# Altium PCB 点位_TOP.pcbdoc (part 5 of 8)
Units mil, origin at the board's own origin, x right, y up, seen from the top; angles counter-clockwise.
Board outline 5129 x 4161 mil, 8 copper layers (Top Layer, GND1, 内层2, VCC, 内层4, Inner5, GND2, Bottom Layer); 288 components, 452 nets, 2040 pads, 1119 vias.
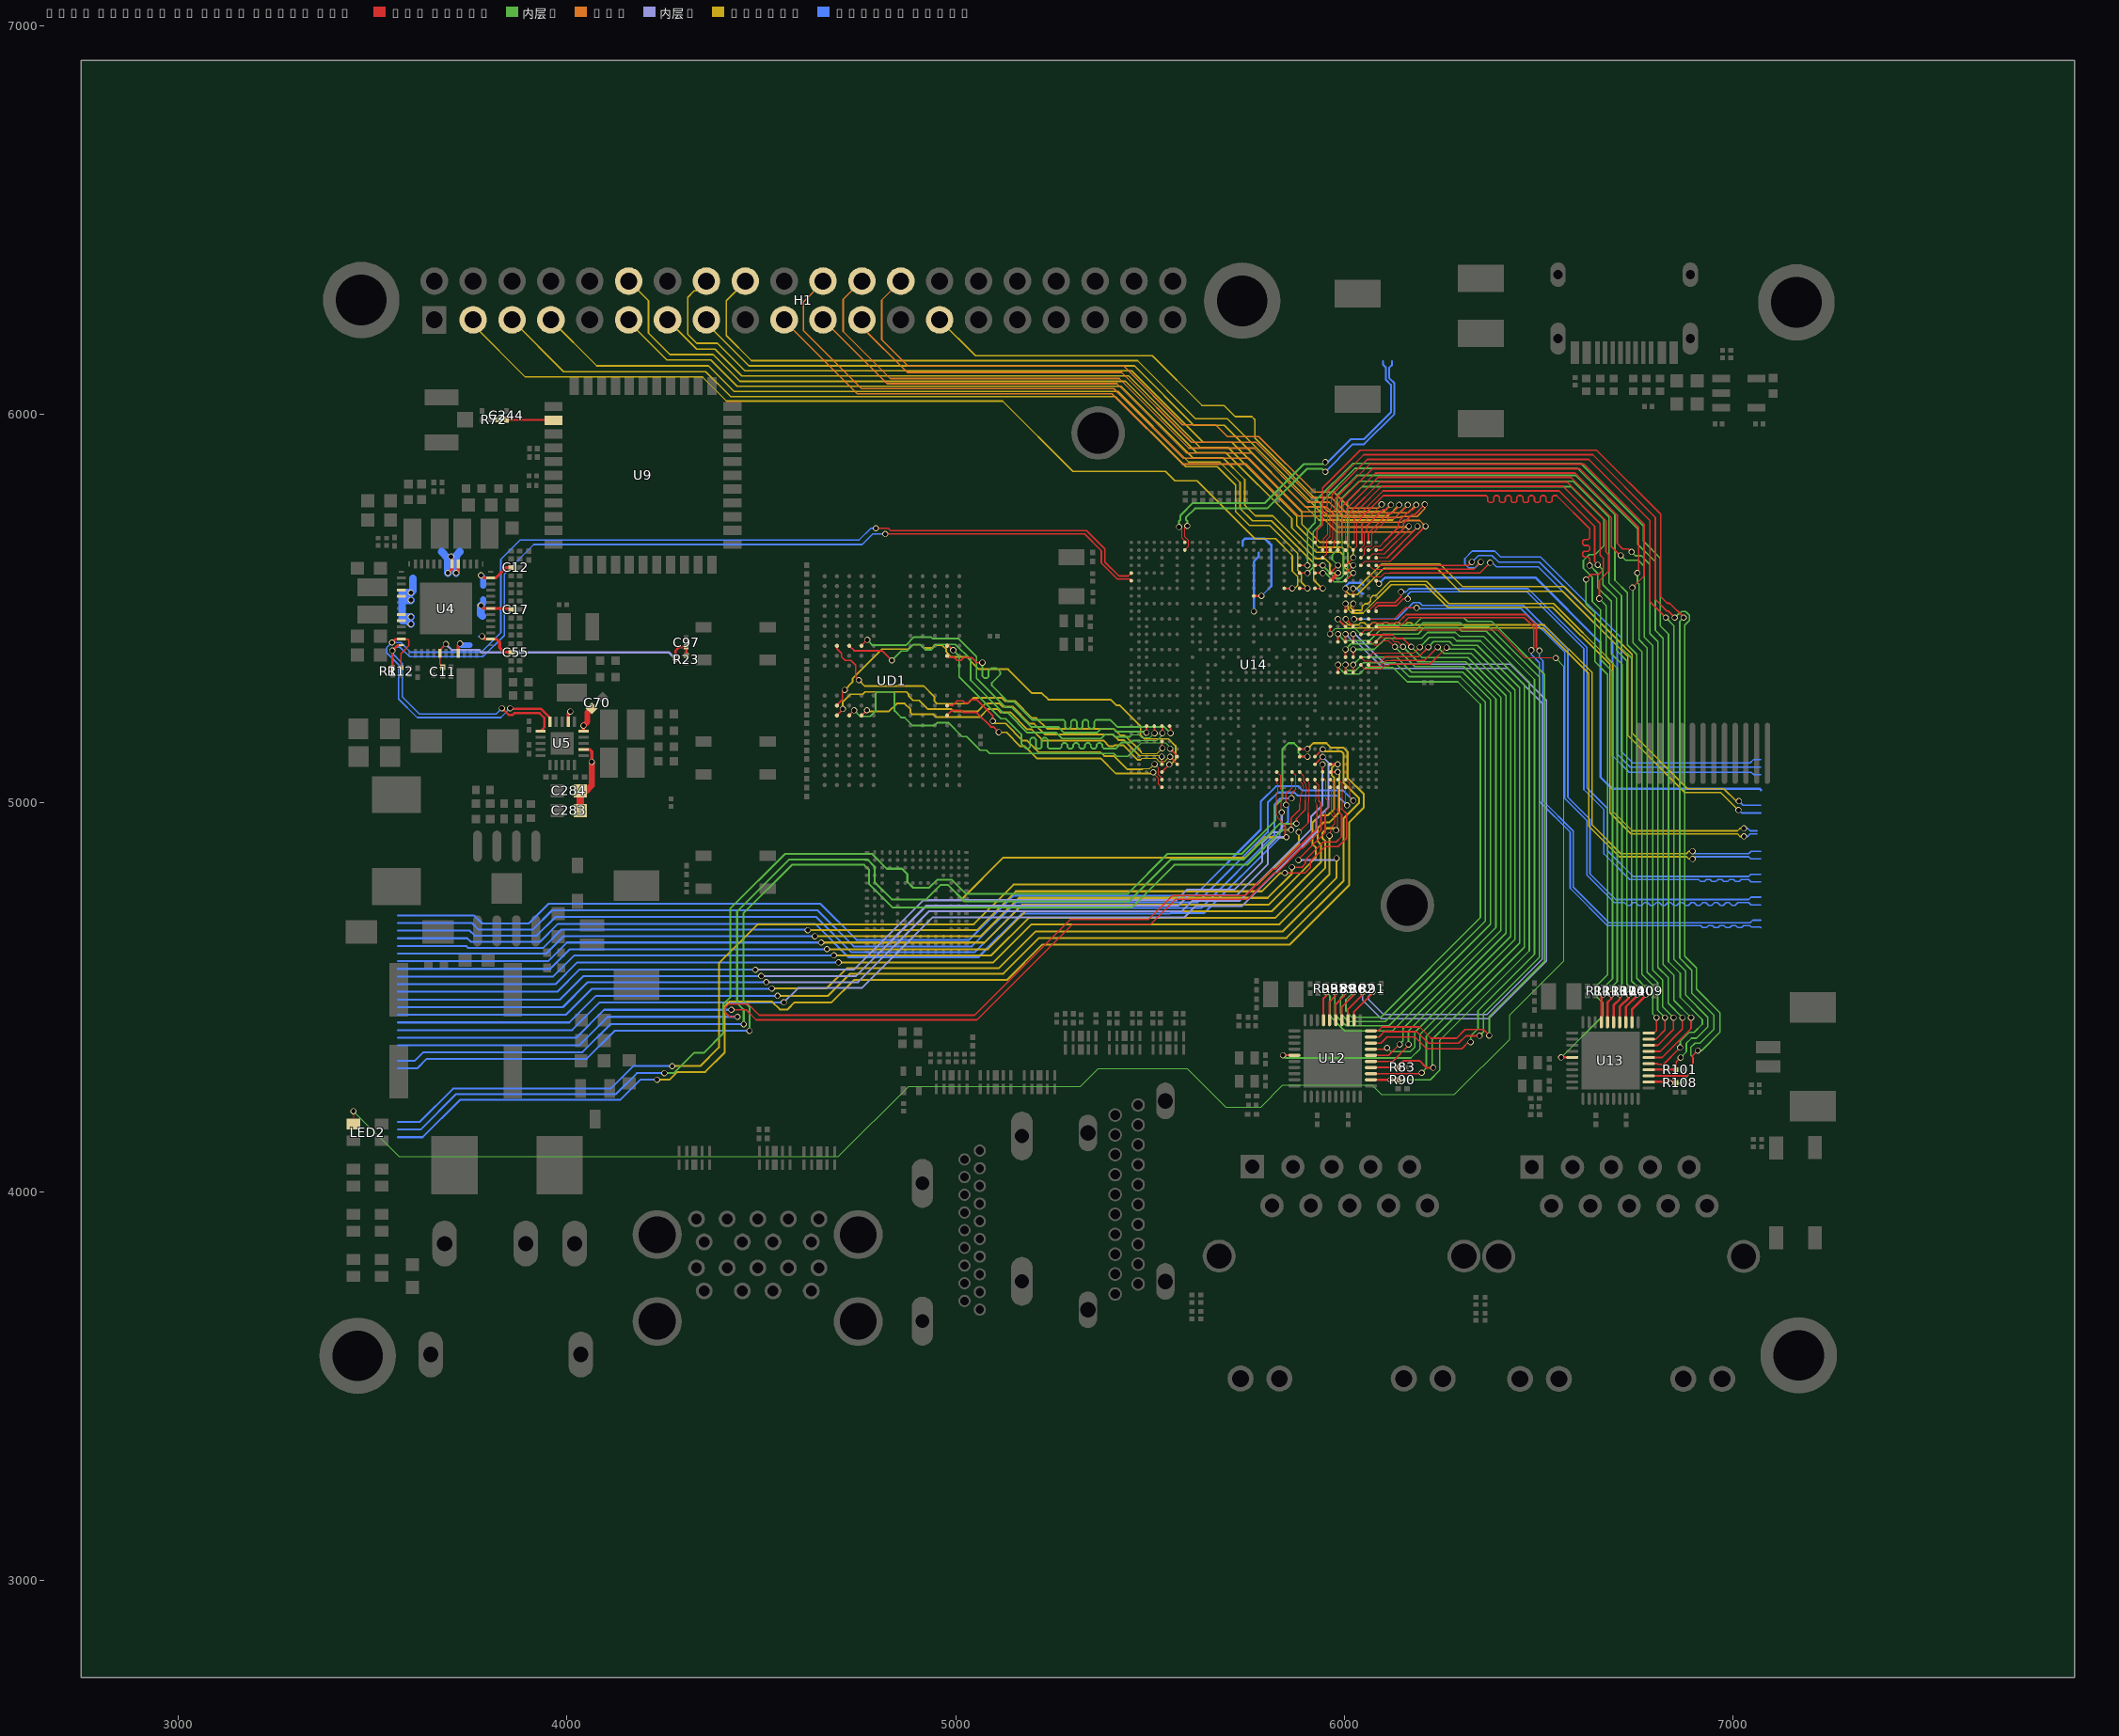
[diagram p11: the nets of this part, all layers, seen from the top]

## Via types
v1: diameter 15.75, hole 11.8, Top Layer to Bottom Layer, 496 vias
v2: diameter 15.7, hole 11.8, Top Layer to Bottom Layer, 335 vias
v3: diameter 15.75, hole 11.81, Top Layer to Bottom Layer, 279 vias
v4: diameter 24, hole 12, Top Layer to Bottom Layer, 9 vias

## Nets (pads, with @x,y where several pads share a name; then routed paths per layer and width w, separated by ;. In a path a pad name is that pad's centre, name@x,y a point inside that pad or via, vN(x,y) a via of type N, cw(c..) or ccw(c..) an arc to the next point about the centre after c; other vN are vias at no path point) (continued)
LCD0-D6: U14.E32 | length 2810.2
  Top Layer w3: U14.E32@6003.23,5060.51 6012.98,5050.75 6012.98,5016.02 v1(6023,5006)
  Bottom Layer w5: 3564.97,4711.06 3760.93,4711.06 3782,4690 3902,4690 3953,4741 4652,4741 4745,4648 5035,4648 5148,4761 5614,4761 5785,4932 5785,5004 5824,5043 5881,5043 5892,5032 5997,5032 v1(6023,5006)
LCD0-D7: U14.E33 | length 2779.1
  Top Layer w3: U14.E33@6003.18,5040.81 6003.18,4997.82 v1(6007,4994)
  Bottom Layer w5: 3564.97,4691.38 3755.62,4691.38 3773,4674 3912,4674 3962,4724 4645,4724 4738,4631 5042,4631 5156,4745 5623,4745 5803,4925 5803,5001 5829,5027 5872,5027 5880,5019 5982,5019 v1(6007,4994)
LCD0-D8: U14.M31 | length 2648.4
  Top Layer w3: U14.M31@5865.45,5080.07 5875.25,5070.27 5875.25,5035.39 5870.86,5031
  Top Layer w4: v1(5864,5012) 5864,5024.14 5870.86,5031
  Bottom Layer w5: 3564.97,4671.69 3750.3,4671.69 3763,4659 3923,4659 3971,4707 4641,4707 4732,4616 5049,4616 5163,4730 5632,4730 5820,4918 5820,4996 5836,5012 v1(5864,5012)
LCD0-D9: U14.M32 | length 2621.5
  Top Layer w3: 5856,5030 5865.45,5039.45 U14.M32@5865.45,5060.37
  Top Layer w4: v1(5850,4995) 5850,5024 5856,5030
  Bottom Layer w5: 3564.97,4652.01 3743.99,4652.01 3753,4643 3931,4643 3977,4689 4639,4689 4725,4603 5058,4603 5170,4715 5551,4715 5553,4717 5640,4717 5834,4911 5834,4931 5855,4952 5855,4990 v1(5850,4995)
LCD0-D10: U14.F32 | length 2730.5
  Top Layer w3: U14.F32@5983.53,5060.51 5993.34,5050.71 5993.34,4985.27
  Top Layer w4: v1(5847,4820) 5899,4820 5913,4834 5913,4850 5951,4888 5984,4888 6006,4910 6006,4972.6 5993.34,4985.27
  Inner5 w5: v1(4620,4673) 5055,4673 5155,4773 5788,4773 5835,4820 v1(5847,4820)
  Bottom Layer w5: 3564.97,4632.32 3740.68,4632.32 3746,4627 3938,4627 3985,4674 4619,4674 v1(4620,4673)
LCD0-D11: U14.F33 | length 2699.4
  Top Layer w3: 5983.48,4985.23 U14.F33@5983.48,5040.81
  Top Layer w4: v1(5865,4835) 5891,4835 5900,4844 5900,4854 5946,4900 5979,4900 5993,4914 5993,4970.05 5983.48,4979.57 5983.48,4985.23
  Inner5 w5: v1(4638,4657) 5064,4657 5163,4756 5803,4756 5865,4818 v1(5865,4835)
  Bottom Layer w5: 3564.97,4612.64 3946.64,4612.64 3991,4657 v1(4638,4657)
LCD0-D12: U14.G30 | length 2782.1
  Top Layer w5: U14.G30@5963.83,5099.56 v1(5982.83,5099.56)
  Inner5 w5: v1(4654,4641) 5074,4641 5171,4738 5805,4738 5927,4860 5927,4885 5918,4894 5918,4949 5937,4968 5957,4968 5974,4985 5974,5065 5968,5071 5968,5091 5976.56,5099.56 v1(5982.83,5099.56)
  Bottom Layer w5: 3564.97,4592.95 3951.95,4592.95 4000,4641 v1(4654,4641)
LCD0-D13: U14.G31 | length 2777.1
  Top Layer w5: U14.G31@5963.83,5079.87 v1(5982.83,5079.87)
  Inner5 w5: v1(4669,4624) 5083,4624 5181,4722 5814,4722 5940,4848 5940,4893 5931,4902 5931,4935 5946,4950 5961,4950 5987,4976 5987,5075.71 v1(5982.83,5079.87)
  Bottom Layer w5: 3564.97,4573.27 3957.26,4573.27 4008,4624 v1(4669,4624)
LCD0-D14: U14.G32 | length 2777.4
  Top Layer w3: U14.G32@5963.88,5060.51 5973.7,5050.69 5973.7,4973.3 5983,4964 5983,4934 v1(5979,4930)
  Inner5 w5: v1(4687,4608) 5092,4608 5189,4705 5823,4705 5951,4833 5951,4902 5944,4909 5944,4924 5955,4935 5974,4935 v1(5979,4930)
  Bottom Layer w5: 3564.97,4553.59 3964.59,4553.59 4019,4608 v1(4687,4608)
LCD0-D15: U14.G33 | length 2745.5
  Top Layer w3: U14.G33@5963.82,5040.51 5966,5038.33 5966,4971 5975,4962 5975,4946 5965,4936 5965,4926 5962,4923 5962,4921 v1@5963.88,4922.88
  Inner5 w5: v1(4699,4590) 5097,4590 5195,4688 5833,4688 5962,4817 v1(5962,4916)
  Bottom Layer w5: 3564.97,4533.9 3970.89,4533.9 4027,4590 v1(4699,4590)
LCD0-D16: U14.P31 | length 2635
  Top Layer w3: U14.P31@5826.15,5080.07 5835.95,5070.27 5835.95,5036.61 5836.36,5036.2 5839.08,5025.26 5839.15,5007.57 5836.45,4999.92 5836.99,4988.57 v1(5839,4976)
  Top Layer w4: v1@5836,4979 v1(5839,4976)
  内层4 w5: v1(4485,4571) 4738,4571 4917,4750 5568,4750 5595,4777 5717,4777 5789,4849 5789,4898 5816,4925 5835,4925 5839,4929 v1(5839,4976)
  Bottom Layer w5: 3564.97,4514.22 3975.22,4514.22 4032,4571 v1(4485,4571)
LCD0-D17: U14.P32 | length 3543
  Top Layer w3: U14.P32@5826.14,5058.6 5828.27,5050.09 5829.02,5046.25 5829.37,5036.98 5829.13,5028.15 5829.13,5028.04 5826,5024.91 5826,4969.64 5828.24,4963.11 5833.8,4956.24 ; 5833.78,4956.22 5846,4944
  Top Layer w4: 5846,4944 5848,4942 5848,4915 v1(5851,4912)
  内层4 w5: v1(4500,4555) 4744,4555 4925,4736 5573,4736 5600,4763 5724,4763 5803,4842 5803,4888 5827,4912 v1(5851,4912)
  Inner5 w5: 5017,4754 5122,4859 5743,4859 5796,4912 v1(5851,4912)
  Bottom Layer w5: 3564.97,4494.52 3982.53,4494.52 4043,4555 v1(4500,4555)
LCD0-D18: U14.H31 | length 2737
  Top Layer w4: v1(5944,5099) 5944.15,5098.85 U14.H31@5944.15,5079.88
  内层4 w5: v1(4513,4539) 4749,4539 4931,4721 5581,4721 5608,4748 5730,4748 5915,4933 5915,4966 5944,4995 v1(5944,5099)
  Bottom Layer w5: 3564.97,4474.85 3989.84,4474.85 4054,4539 v1(4513,4539)
LCD0-D19: U14.H32 | length 2961.3
  Top Layer w3: U14.H32@5944.18,5060.51 5945.1,5061.43 5950,5061.43 5953,5058.43 5953,5010.7 5958.74,5004.96 5958.74,4985.74 5951,4978 5951,4971
  Top Layer w4: v1(5882,4853) 5882,4855 5951,4924 5951,4971
  内层4 w5: v1(5882,4853) 5975,4853 v1(5980,4858)
  Inner5 w5: v1(4527,4523) 4668,4523 4720,4575 5111,4575 5206,4670 5842,4670 5980,4808 v1(5980,4858)
  Bottom Layer w5: 3564.97,4455.15 3997.16,4455.15 4064,4522 4526,4522 v1(4527,4523)
LCD0-D20: U14.J29 | length 3030.2
  Top Layer w4: U14.J29@5924.46,5119.25 5943.46,5138.25 v1(5944.46,5138.25)
  Inner5 w5: v1(4542,4504) 4672,4504 4729,4561 5123,4561 5215,4653 5851,4653 5998,4800 5998,4960 6038,5000 6038,5012 5998,5052 5998,5127 5992,5133 5949.71,5133 v1(5944.46,5138.25)
  Bottom Layer w5: 3564.97,4435.48 4006.47,4435.48 4075,4504 v1(4542,4504)
LCD0-D21: U14.J30 | length 2813.7
  Top Layer w4: U14.J30@5924.46,5099.56 5943.46,5118.56 v1(5944.46,5118.56)
  内层4 w5: v1(4558,4487) 4595,4524 4759,4524 4941,4706 5589,4706 5618,4735 5737,4735 5928,4926 5928,4958 5959,4989 5959,5104.02 v1(5944.46,5118.56)
  Bottom Layer w5: 3564.97,4415.78 4013.78,4415.78 4085,4487 v1(4558,4487)
LCD0-D22: U14.J32 | length 2754.7
  Top Layer w3: U14.J32@5924.48,5060.51 5924.48,5054.71 5934.27,5044.91 5934.27,5005.56
  Top Layer w4: v1(4423,4468) 4461,4468 4487,4442 5055,4442 5301,4688 5502,4688 5566,4752 5751,4752 5819,4820 5826,4820 5890,4884 5894,4884 5940.04,4930.04 5940.04,4999.8 5934.27,5005.56
  Bottom Layer w5: 3564.97,4396.1 4024.11,4396.1 4096,4468 v1(4423,4468)
LCD0-D23: U14.J33 | length 2797.3
  Top Layer w3: U14.J33@5924.31,5040.15 5926.01,5034.28 5926.16,5014.28 5925.23,5003.47 5929.75,4994.05
  Top Layer w4: v1(4439,4450) 4419,4450 4408,4461 4408,4474 4417,4483 4466,4483 4495,4454 5049,4454 5295,4700 5496,4700 5558,4762 5746,4762 5814,4830 5823,4830 5887,4894 5890,4894 5929.75,4933.75 5929.75,4994.05 5929.75,4994.35
  Bottom Layer w5: 3564.97,4376.41 4031.41,4376.41 4105,4450 v1(4439,4450)
LCD0-DE: U14.K32 | length 2919.7
  Top Layer w3: 5906.88,4974.2 5906.88,4997.45 5908.54,5020.82 5908.56,5021.22 5907.94,5033.02 5908.5,5041.47 5908.53,5048.86 5904.77,5060.51 U14.K32@5907.18,5058.11
  Top Layer w4: v1(5883,4925) 5907.18,4949.18 5907.18,4974
  Inner5 w5: v1(4271,4323) 4343,4323 4391,4371 4391,4588 4491,4688 5047,4688 5149,4790 5776,4790 5883,4897 v1(5883,4925)
  Bottom Layer w5: 3564.97,4179.56 3621.57,4179.56 3707,4265 4113,4265 4171,4323 v1(4271,4323)
LCD0-HSYNC: U14.L28 | length 3317
  Top Layer w5: U14.L28@5885.09,5138.93 v1(5905.09,5138.93)
  Inner5 w5: v1(4232,4288) 4264,4288 4284,4308 4356,4308 4406,4358 4406,4477 4418,4489 4528,4489 4548,4469 4568,4469 4586,4487 4681,4487 4739,4545 5132,4545 5223,4636 5860,4636 6012,4788 6012,4950 6050,4988 6050,5023 6008.32,5064.68 6008.32,5131.68 5997,5143 5965,5143 5954,5154 5920.16,5154 v1(5905.09,5138.93)
  Bottom Layer w5: 3564.97,4140.19 3629.2,4140.19 3725,4236 4137,4236 4189,4288 v1(4232,4288)
LCD0-PWM: U14.L31 | length 3050.8
  Top Layer w3: U14.L31@5885.15,5080.07 5894.98,5070.24 5895.03,5059.01 5896.04,5055.11 5898.18,5052.43 5901.72,5040.93 5898.86,5017.8 5899,5005.68 5899.01,5005.17
  Top Layer w4: v1(5877,4947) 5877,4960 5899,4982 5899,5005.68 5899,5006
  内层2 w5: v1(4455,4431) 4455,4468 4438,4485 4438,4721 4572,4855 4773,4855 4792,4836 4792,4796 4836,4752 4924,4752 4961,4789 4981,4789 5023,4747 5446,4747 5554,4855 5742,4855 5834,4947 v1(5877,4947)
  Bottom Layer w5: 3564.97,4337.05 3609.05,4337.05 3631,4359 4040,4359 4112,4431 v1(4455,4431)
LCD0-RST: U14.L32 | length 3006.3
  Top Layer w3: U14.L32@5884.76,5058.85 5892.33,5049.35 5894.8,5041.31 5893.95,5034.44 5891.48,5029.57 5887.54,5020.69 5884.84,4996.2
  Top Layer w4: v1(5863,4931) 5863,4961 5884.8,4982.8 5884.8,4996.42
  内层2 w5: v1(4470,4414) 4470,4476 4454,4492 4454,4716 4579,4841 4765,4841 4777,4829 4777,4792 4838,4731 5453,4731 5563,4841 5750,4841 5840,4931 v1(5863,4931)
  Bottom Layer w5: 3564.97,4317.36 3615.36,4317.36 3640,4342 4051,4342 4123,4414 v1(4470,4414)
LCD0-VSYNC: U14.L29 | length 3182.7
  Top Layer w5: U14.L29@5885.09,5119.25 v1(5905.09,5119.25)
  内层2 w5: v1(4251,4305) 4275,4305 4327,4357 4352,4357 4402,4407 4402,4482 4420,4500 4420,4728 4561,4869 4785,4869 4823,4831 4862,4831 4876,4817 4876,4797 4891,4782 4932,4782 4953,4803 4990,4803 5027,4766 5442,4766 5545,4869 5736,4869 5823,4956 5823,4993 5841,5011 5841,5139 5856,5154 5870.33,5154 5882,5142.33 5882,5129 5891.75,5119.25 v1(5905.09,5119.25)
  Bottom Layer w5: 3564.97,4159.89 3623.89,4159.89 3715,4251 4126,4251 4180,4305 v1(4251,4305)
LEDC: LED2.3 U14.C13 | length 4864.7
  Top Layer w3: v2(3451,4207) 3451.16,4206.84 LED2.3@3451.16,4174.43 ; U14.C13@6042.57,5434.21 6052.36,5444 6395,5444 6466,5373 v2(6544,5373)
  内层2 w3: v2(3451,4207) 3569,4089 4697,4089 4878,4270 5320,4270 5366,4316 5597,4316 5696,4217 5784,4217 5840,4273 6072,4273 6096,4249 6282,4249 6424,4391 6424,4453 6564,4593 6564,5353 v2(6544,5373)
MCSI0-CKN: U14.A10 | length 1629.1
  Top Layer w4: U14.A10@6081.94,5493.27 6079.93,5495.28 6079.93,5500.93 6087,5508 6134.16,5508 6151.16,5525 v2(6163,5525)
  Bottom Layer w4: v2(6163,5525) 6163,5536 6170.34,5543.34 6469.66,5543.34 6616,5397 6616,5035 6668,4983 6668,4869 6734.06,4802.94 6911.21,4802.94 6916.21,4797.94 6926.21,4797.94 6931.21,4802.94 6941.21,4802.94 6946.21,4797.94 6956.21,4797.94 6961.21,4802.94 6971.21,4802.94 6976.21,4797.94 6986.21,4797.94 6991.21,4802.94 7001.21,4802.94 7006.21,4797.94 7016.21,4797.94 7021.21,4802.94 7040.56,4802.94 7046.4,4797.1 7072.02,4797.1
MCSI0-CKP: U14.B10 | length 1625.8
  Top Layer w4: U14.B10@6062.26,5493.26 6062.26,5494.33 6083.93,5516 6130.84,5516 6146,5531.16 v2(6146,5543)
  Bottom Layer w4: v2(6146,5543) 6158.69,5543 6167.03,5551.34 6472.66,5551.34 6624,5400 6624,5039 6677,4986 6677,4877 6743.06,4810.94 7040.56,4810.94 7046.4,4816.78 7072.02,4816.78
MCSI0-D0N: U14.A12 | length 1690.5
  Top Layer w3: U14.A12@6081.94,5453.9 6141.9,5453.9 6158,5470
  Top Layer w4: 6158,5470 6165,5477 6463,5477 6487,5453 6487,5399 v2(6481,5393)
  Bottom Layer w4: v2(6481,5393) 6481,5382 6502,5361 6502,5004 6581,4925 6581,4780.69 6676.69,4685 6916.73,4685 6921.73,4680 6931.73,4680 6936.73,4685 6946.73,4685 6951.73,4680 6961.73,4680 6966.73,4685 6976.73,4685 6981.73,4680 6991.73,4680 6996.73,4685 7006.73,4685 7011.73,4680 7021.73,4680 7026.73,4685 7043,4685 7047,4681 7070.02,4681 7072.02,4678.99
MCSI0-D0P: U14.B12 | length 1692.6
  Top Layer w3: U14.B12@6062.26,5453.91 6072.36,5464 6138,5464 6150,5476
  Top Layer w4: 6150,5476 6159,5485 6466.31,5485 6494,5457.31 6494,5400 v2(6502,5392)
  Bottom Layer w4: v2(6502,5392) 6502,5375 6511,5366 6511,5006 6589,4928 6589,4784 6681,4692 7044,4692 7050.68,4698.68 7072.02,4698.68
MCSI0-D1N: U14.B11 | length 1700.5
  Top Layer w3: U14.B11@6062.26,5473.58 6128.58,5473.58 6137,5482
  Top Layer w4: 6137,5482 6157,5502 v2(6186,5502)
  Bottom Layer w4: v2(6186,5502) 6187.68,5500.32 6454.68,5500.32 6567.05,5387.95 6567.05,5011.95 6624,4955 6624,4814.53 6694.64,4743.89 6720.08,4743.89 6727.33,4736.65 6735.08,4736.65 6742.33,4743.89 6750.08,4743.89 6757.33,4736.65 6765.08,4736.65 6772.33,4743.89 6780.08,4743.89 6787.33,4736.65 6795.08,4736.65 6802.33,4743.89 6810.08,4743.89 6817.33,4736.65 6825.08,4736.65 6832.33,4743.89 6840.08,4743.89 6847.33,4736.65 6855.08,4736.65 6862.33,4743.89 6870.08,4743.89 6877.33,4736.65 6885.08,4736.65 6892.33,4743.89 6900.08,4743.89 6907.33,4736.65 6915.08,4736.65 6922.33,4743.89 6930.08,4743.89 6937.33,4736.65 6945.08,4736.65 6952.33,4743.89 6960.08,4743.89 6967.33,4736.65 6975.08,4736.65 6982.33,4743.89 6990.08,4743.89 6997.33,4736.65 7005.08,4736.65 7012.33,4743.89 7040.56,4743.89 7046.4,4738.05 7072.02,4738.05
MCSI0-D1P: U14.C11 | length 1705.2
  Top Layer w5: v2(6025,5473) 6042,5473 U14.C11@6042.58,5473.58
  Bottom Layer w4: v2(6025,5473) 6135,5473 6177.35,5515.35 6193.65,5515.35 6200.68,5508.32 6460.68,5508.32 6575.05,5393.95 6575.05,5014.95 6632,4958 6632,4817.84 6697.95,4751.89 7040.56,4751.89 7046.4,4757.73 7072.02,4757.73
MCSI0-D2N: U14.E12 | length 1606.8
  Top Layer w4: v1(5983.2,5472.9) 5984.2,5472.9 U14.E12@6003.2,5453.9
  Inner5 w4: v1(5983.2,5472.9) 6005.75,5450.34 6511.34,5450.34 6629,5332.69 6629,4940.69 6707.69,4862 6880.15,4862 6886.15,4856 v2(6896,4856)
  Bottom Layer w4: v2(6896,4856) 6902,4862 7040.56,4862 7046.4,4856.15 7072.02,4856.15
MCSI0-D2P: U14.D12 | length 1607.1
  Top Layer w4: v1(6004,5473) 6022.9,5454.1 U14.D12@6022.9,5453.9
  Inner5 w4: v1(6004,5473) 6004,5465 6010.66,5458.34 6036.66,5458.34 6041.66,5463.34 6051.66,5463.34 6056.66,5458.34 6066.66,5458.34 6071.66,5463.34 6081.66,5463.34 6086.66,5458.34 6096.66,5458.34 6101.66,5463.34 6111.66,5463.34 6116.66,5458.34 6126.66,5458.34 6131.66,5463.34 6141.66,5463.34 6146.66,5458.34 6156.66,5458.34 6161.66,5463.34 6171.66,5463.34 6176.66,5458.34 6514.66,5458.34 6637,5336 6637,4944 6711,4870 6880.15,4870 6886.15,4876 v2(6896,4876)
  Bottom Layer w4: v2(6896,4876) 6902,4870 7040.56,4870 7046.4,4875.85 7072.02,4875.85
MCSI0-D3N: U14.E10 | length 1619.2
  Top Layer w4: v1(6003,5513) 6003,5493.47 U14.E10@6003.2,5493.27
  Inner5 w4: v1(6003,5513) 6010,5506 6010,5498.1 6019.44,5488.66 6047.66,5488.66 6121,5562 6208,5562 6266,5504 6536,5504 6683,5357 6683,4974.69 6737.38,4920.3 7011.55,4920.3 7017.86,4914 v2(7028,4914)
  Bottom Layer w4: v2(7028,4914) 7037.85,4914 7044.15,4920.3 7062.34,4920.3
MCSI0-D3P: U14.D10 | length 1616.6
  Top Layer w4: U14.D10@6022.9,5493.27 6022.9,5512.9 v1(6023,5513)
  Inner5 w4: v1(6023,5513) 6017,5507 6017,5501 6022.34,5495.66 6043.34,5495.66 6046.01,5498.33 6046.01,5506.01 6052.78,5512.78 6060.46,5512.78 6067.23,5519.54 6067.23,5527.23 6073.99,5533.99 6081.68,5533.99 6117.69,5570 6211.31,5570 6268.31,5513 6538.31,5513 6691,5360.31 6691,4978 6740.7,4928.3 7011.55,4928.3 7017.86,4934.61 v2(7027.71,4934.61)
  Bottom Layer w4: v2(7027.71,4934.61) 7037.85,4934.61 7044.15,4928.3 7062.34,4928.3
MCSI0-MCLK: U14.A6 | length 1429.7
  Top Layer w6: U14.A6@6081.94,5572.01 6081.94,5571.06 v2(6089,5564)
  Bottom Layer w6: v2(6089,5564) 6105,5580 6492,5580 6659,5413 6659,5067 6689.89,5036.11 7069.24,5036.11 7072.02,5033.32
MCSI0-PWDN: U14.B4 | length 1534
  Top Layer w3: U14.B4@6064.06,5610.26 6074.92,5601.77 6084.19,5601.46 6089.96,5601.82 6105.25,5601.87
  Top Layer w4: 6104.98,5602 6333,5602 v2(6351,5620)
  Bottom Layer w4: v2(6351,5620) 6336,5605 6320,5605 6310,5615 6310,5629 6329,5648 6387,5648 6402,5633 6505,5633 6713,5425 6713,5132 6742,5103 7044,5103 7053.06,5112.06 7072.02,5112.06
MCSI0-RSTN: U14.A4 | length 1398.5
  Top Layer w4: U14.A4@6081.94,5611.39 6319.39,5611.39 v2(6328,5620)
  Bottom Layer w4: v2(6328,5620) 6345,5637 6380,5637 6397,5620 6502,5620 6702,5420 6702,5126 6735.62,5092.38 7072.02,5092.38
MCSI0-SCK: U14.E8 | length 1561.8
  Top Layer w4: U14.E8@6003.2,5532.64 v1(6003.2,5551.64)
  Inner5 w4: v1(6003.2,5551.64) 6003.2,5545.8 6013,5536 6034,5536 6102,5604 6238,5604 6297,5545 6561,5545 6729,5377 6729,5174 6876,5027 6968,5027 7013,4982 v2(7014,4982)
  Bottom Layer w4: v2(7014,4982) 7021.73,4974.27 7072.02,4974.27
  Bottom Layer w6: v1(6003.2,5551.64) 6003.2,5557.2 6012,5566 6044.49,5566 6048.49,5562
MCSI0-SDA: U14.D8 | length 1501.4
  Top Layer w4: U14.D8@6022.89,5532.64 v1(6022.89,5551.64)
  Inner5 w4: v1(6022.89,5551.64) 6032.64,5551.64 6096,5615 6246,5615 6304,5557 6566,5557 6740,5383 6740,5180 6883,5037 6976,5037 7008,5005 v2(7015,5005)
  Bottom Layer w4: v2(7015,5005) 7026.05,4993.95 7072.02,4993.95
  Bottom Layer w6: v1(6022.89,5551.64) 6032.36,5551.64 6045,5539 6048.49,5539
MCSI0-USER: U14.B5 | length 1427.4
  Top Layer w3: U14.B5@6062.26,5591.69 6071.95,5582 6094,5582 6104,5592 6115.91,5592
  Top Layer w4: 6115.91,5592 6349,5592 v2(6375,5618)
  Bottom Layer w4: v2(6375,5618) 6381,5618 6391,5608 6499,5608 6690,5417 6690,5122 6733,5079 7047,5079 7053.31,5072.69 7072.02,5072.69
MICIN3N: U14.AF1 | length 869.5
  Top Layer w3: v1(5575,5710) 5576.32,5710 5582.69,5703.63 5582.69,5681.54 5589.69,5674.54 U14.AF1@5589.69,5670.41
  内层2 w5: v1(5575,5710) 5575,5725.71 5578.5,5729.21 5578.5,5740.01 5610.49,5772 5796,5772 5896,5872 5946,5872 v2(5951,5877)
  Bottom Layer w5: v2(5951,5877) 5958,5877 6017,5936 6051,5936 6120,6005 6120,6076.27 6106.76,6089.51 6106.76,6120.23 6099.76,6127.23 6099.76,6136.99
MICIN3P: U14.AF2 | length 893.7
  Top Layer w3: U14.AF2@5589.69,5650.71 5599.49,5660.51 5599.49,5675.79 5589.69,5685.59 5589.69,5706.53 v1(5596,5712.84) v1@5596,5713
  内层2 w5: v1(5596,5712.84) 5596,5725.71 5592.5,5729.21 5592.5,5734.21 5616.29,5758 5801.8,5758 5903.8,5860 5943,5860 v2(5951,5852)
  Bottom Layer w5: v2(5951,5852) 6022,5923 6050.73,5923 6129,6001.27 6129,6080 6115.76,6093.24 6115.76,6120.23 6122.76,6127.23 6122.76,6136.99
PE0: H1.12 U14.E6 | length 2282.3
  Top Layer w4: U14.E6@6003.2,5572.01 6023,5591.8 v1(6023,5592)
  Inner5 w4: H1.12@4159,6343 4210,6292 4210,6209 4265,6154 4376,6154 4445,6085 5437,6085 5620,5902 5695,5902 5865,5732 5865,5708 5928,5645 5990,5645 5997.37,5637.63 5997.37,5609.63 6015,5592 v1(6023,5592)
PE1: H1.21 U14.C4 | length 1981.7
  Top Layer w3: U14.C4@6042.32,5611.32 6052.23,5621.23 6117.21,5621.21 6123,5627
  Top Layer w4: 6123,5627 6208,5712 v1(6209,5712)
  VCC w4: H1.21@4659,6243 4660,6243 4824,6079 5415,6079 5594,5900 5761,5900 5899,5762 5954,5762 5993,5723 6148,5723 6152,5727 6194,5727 v1(6209,5712)
PE2: H1.13 U14.E5 | length 2082
  Top Layer w4: U14.E5@6003.2,5591.69 v1(6023.2,5611.69)
  Inner5 w4: H1.13@4259,6243 4334,6168 4381,6168 4450,6099 5445,6099 5629,5915 5701,5915 5878,5738 5878,5714 5934,5658 5995,5658 6009,5644 6009,5620.24 6016.6,5612.64 6022.26,5612.64 v1(6023.2,5611.69)
PE3: H1.16 U14.E4 | length 2168.4
  Top Layer w4: U14.E4@6003.2,5611.38 v1(6023.2,5631.38)
  Inner5 w4: H1.16@4359,6343 4333.57,6317.57 4327.57,6317.57 4311,6301 4311,6206 4334,6183 4387,6183 4458,6112 5453,6112 5637,5928 5711,5928 5891,5748 5891,5717 5937,5671 6003,5671 6023.2,5650.8 v1(6023.2,5631.38)
PE4: H1.15 U14.C3 | length 2240.7
  Top Layer w3: U14.C3@6042.49,5631.01 6052.31,5640.83 6052.31,5654.77 6058.1,5660.55 6067.72,5660.55 6071.75,5664.58 6071.75,5692.56 6113.19,5734 6121,5734
  Top Layer w4: 6121,5734 6131,5734 6163,5766 v1(6163,5767)
  Inner5 w4: H1.15@4359,6243 4359,6234 4468,6125 5460,6125 5613,5972 5691,5972 5935,5728 6124,5728 v1(6163,5767)
PE5: H1.22 U14.B3 | length 2057.8
  Top Layer w3: U14.B3@6062.19,5631.01 6072.08,5640.9 6102.9,5640.9 6107,5645
  Top Layer w4: 6107,5645 6166,5704 v1(6166,5712)
  VCC w4: H1.22@4659,6343 4659,6340 4609,6290 4609,6215 4758,6066 5407,6066 5586,5887 5754,5887 5892,5749 5947,5749 5986,5710 6164,5710 v1(6166,5712)
PE6: H1.19 U14.A3 | length 2005.1
  Top Layer w3: U14.A3@6081.89,5631.01 6109.95,5630.95
  Top Layer w4: 6109.95,5630.95 6188,5709 v1(6188,5712)
  VCC w4: H1.19@4559,6243 4559,6241 4747,6053 5402,6053 5583,5872 5748,5872 5882,5738 5940,5738 5980.88,5697.12 6175.12,5697.12 6188,5710 v1(6188,5712)
PE7: H1.24 U14.A2 | length 2046.4
  Top Layer w4: U14.A2@6081.94,5650.74 6096.74,5650.74 6152,5706 6152,5720 6174,5742 6181,5742 v1(6207,5768)
  VCC w4: H1.24@4759,6343 4758,6343 4711,6296 4711,6213 4832,6092 5421,6092 5600,5913 5768,5913 5907,5774 5961,5774 6000,5735 6144,5735 6146,5737 6187,5737 6207,5757 v1(6207,5768)
PE8: H1.23 U14.B2 | length 1831.6
  Top Layer w3: U14.B2@6062.19,5650.71 6067.4,5650.71 6076.93,5660.24 6090.24,5660.24 6104,5674
  Top Layer w4: 6104,5674 6139,5709 6139,5723 6170,5754 6175.66,5754 6185,5763.34 v1(6185,5767)
  VCC w4: H1.23@4759,6243 4759,6225 4876,6108 5427,6108 5607,5928 5773,5928 5915,5786 5966,5786 6005,5747 6165,5747 v1(6185,5767)
PE9: H1.18 U14.B1 | length 2230.2
  Top Layer w4: U14.B1@6062.19,5670.41 6062.13,5695.03 6112.1,5745 6122,5745 6141,5764 v1(6141,5767)
  Inner5 w4: H1.18@4459,6343 4459,6341 4410,6292 4410,6203 4475,6138 5468,6138 5617,5989 5699,5989 5949,5739 6113,5739 v1(6141,5767)
PE10: H1.27 U14.C2 | length 1552.7
  Top Layer w3: U14.C2@6042.49,5650.71 6042.49,5655.23 6052.3,5665.06 6052.3,5696.11 6057.9,5701.71
  Top Layer w4.5: 6057.9,5701.71 6057.9,5712.71 6100.19,5755 6106.55,5755 6118.55,5767 v1(6120,5767)
  Inner5 w4: H1.27@4959,6243 5051,6151 5506,6151 5634,6023 5690,6023 5719,5994 5762,5994 5770,5986 5770,5939 5959,5750 6103,5750 v1(6120,5767)
PE11: H1.7 U14.J7 | length 2356
  Top Layer w4: U14.J7@5924.46,5552.32 v1(5944.46,5552.32)
  Inner5 w4: H1.7@3959,6243 4077,6125 4364,6125 4430,6059 5418,6059 5600,5877 5680,5877 5732,5825 5732,5758 5764,5726 5812,5726 5921,5617 5921,5574 5942.68,5552.32 v1(5944.46,5552.32)
PE12: H1.26 U14.C1 | length 1760.1
  Top Layer w4: U14.C1@6042.57,5670.43 6045,5672.86 6045,5717 v1(6096,5768)
  VCC w4: H1.26@4859,6343 4810,6294 4810,6192 4878,6124 5433,6124 5584,5973 5669,5973 5699,5943 5780,5943 5923,5800 5973,5800 6014,5759 6087,5759 v1(6096,5768)
PE13: H1.11 U14.G6 | length 2174.9
  Top Layer w10: U14.G6@5963.83,5572.01 v1(5983.83,5592.01)
  Inner5 w4: H1.11@4159,6243 4159,6238 4257,6140 4370,6140 4438,6072 5426,6072 5610,5888 5688,5888 5744,5832 5744,5766 5771,5739 5816,5739 5926,5629 5950,5629 5963,5616 5963,5598 5969,5592 v1(5983.83,5592.01)
PE14: H1.5 U14.L7 | length 2429.8
  Top Layer w4: U14.L7@5885.09,5552.32 v1(5905.09,5552.32)
  Inner5 w4: H1.5@3859,6243 3992,6110 4357,6110 4421,6046 5411.41,6046 5592.41,5865 5673,5865 5720,5818 5720,5750 5756,5714 5808,5714 5880,5642 5880,5599 5890,5589 5890,5567.41 v1(5905.09,5552.32)
PE15: H1.3 U14.N7 | length 2485.9
  Top Layer w4: U14.N7@5845.72,5552.32 v1(5865.72,5552.32)
  Inner5 w4: H1.3@3759,6243 3759,6230 3893,6096 4349,6096 4411,6034 5121,6034 5302,5853 5540,5853 5564,5829 5621,5829 5770,5680 5823,5680 5866,5637 5866,5597 5880,5583 5880,5560 5872.32,5552.32 v1(5865.72,5552.32)
PGAOUT0: U14.U8 | length 256.1
  Top Layer w6: U14.U8@5766.98,5532.64 5767.34,5533 v1(5787,5533)
  Bottom Layer w3: v1(5787,5533) 5811,5557
  Bottom Layer w6: 5738,5662.51 5738,5674 5744,5680 5796,5680 5811.98,5664.02 5811.98,5557.98 5811,5557
PGAOUT1: U14.U10 | length 155.9
  Bottom Layer w6: v1(5766.98,5493.27) 5766.98,5621 5779.51,5633.53 5779.51,5644
PHYRSTB0: R90.2 U12.12 U14.D16 | length 1846.9
  Top Layer w5: U14.D16@6022.89,5375.16 v1(6022.89,5395.16) ; U12.12@6068.4,4287.9 v1(6119.2,4287.9) 6140.39,4287.9 R90.2@6140.49,4288
  内层2 w4: v1(6022.89,5395.16) 6077.16,5395.16 6106,5424 6199,5424 6214,5439 6286,5439 6296,5429 6358,5429 6476,5311 6476,4620 6245,4389 6245,4312 6221,4288 6183,4288 6182.9,4287.9 v1(6119.2,4287.9)
PHYRSTB1: R108.2 U13.12 U14.J1 | length 2805.1
  Top Layer w4: U14.J1@5924.46,5670.44 5930,5675.98 5930,5702 5944,5716 5944,5810.72 6041.28,5908 6649,5908 6814,5743 6814,5531 6831,5514 6837,5514 6873,5478 v1(6873,5477)
  Top Layer w6: U13.12@6783.31,4282.41 6851.61,4282.41 R108.2@6853.49,4280.53
  内层2 w4: v1(6838,4279) 6864,4279 6897,4312 6897,4346 6891,4352 6891,4371 6902,4382 6915,4382 6951,4418 6951,4454 6894,4511 6894,4570 6863,4601 6863,5467 v1(6873,5477)
PMU-SCK: R11.2 U4.52 U5.6 U14.AN6 | length 2850.1
  Top Layer w4: v2(4819,5692) 5332.03,5692 5375,5649.03 5375,5617 5416,5576 5448.03,5576 U14.AN6@5452.02,5572.01
  Top Layer w6: R11.2@3551.77,5348.28 3551.77,5391.23 v1(3551,5392) 3564.98,5405.98 U4.52@3574.26,5405.98 ; v1(3833,5244) 3850,5227 3861,5227 3865,5231 3930,5231 3942,5219 3942,5194.56 U5.6@3932.43,5184.99
  Bottom Layer w4: v1(3833,5244) 3818,5229 3621,5229 3577,5273 3577,5359 3551,5385 v1(3551,5392) 3560,5401 3570.62,5401 3594.62,5377 3785,5377 3839,5431 3839,5589 3915,5665 4760,5665 4787,5692 v2(4819,5692)
PMU-SDA: R12.2 U4.51 U5.5 U14.AN5 | length 2960
  Top Layer w3: U14.AN5@5451.69,5591.36 U14.AN5@5451.95,5591.36
  Top Layer w4: R12.2@3572.77,5348.28 3572.77,5383.77 3594,5405 3594,5418 3591,5421 3574.98,5421 U4.51@3574.25,5421.73 ; v2(4795,5707) 4827,5707 4833,5701 5337,5701 5384,5654 5384,5620 5420,5584 5444.34,5584 5451.69,5591.36 U14.AN5@5452.02,5591.69
  Top Layer w6: v1(3550,5413) 3558.73,5421.73 U4.51@3574.25,5421.73 ; v1(3854,5244) 3856,5242 3934,5242 3956.34,5219.66 U5.5@3956.34,5208.9
  Bottom Layer w4: v1(3854,5244) 3830,5220 3615,5220 3567,5268 3567,5356 3537,5386 3537,5400 v1(3550,5413) 3573,5413 3598,5388 3780,5388 3830,5438 3830,5627 3880,5677 4752,5677 4782,5707 v2(4795,5707)
PS: C12.1 C17.1 C55.1 C70.2 C283.2 C284.2 U4.9 U4.15 U4.20 U4.25 U4.31 U4.32 U4.43 U4.44 U4.47 U4.48 U5.2 U5.17 U5.20 | length 1100.9
  Top Layer w8: v1(3694,5592) 3704.86,5602.86 U4.32@3704.86,5615.33 3704.86,5631.14 v1(3702,5634) ; v1(3715,5592) 3720.61,5597.61 U4.31@3720.61,5615.33 ; U4.9@3720.61,5385.61 3720.61,5405.61 v1(3725,5410) ; v1(3779,5508) 3786.53,5500.47 U4.20@3803.97,5500.47 3854.03,5500.47 C17.1@3856.5,5498 ; v1(3779,5586) 3785.79,5579.21 U4.25@3803.97,5579.21 3817.21,5579.21 3844,5606 C12.1@3856.5,5606 ; v1(3782,5429) 3789.27,5421.73 U4.15@3803.97,5421.73 3819.27,5421.73 3827,5414 3827,5400 3839,5388 C55.1@3856.5,5388 ; U5.2@4003.59,5208.9 4003.59,5230.24 v1(4008.84,5235.49) ; v1(4043,5199) 4043.25,5198.75 U5.20@4043.25,5184.99 ; U5.17@4043.25,5137.74 4058.26,5137.74 4064,5132 v1(4064,5106)
  Top Layer w15: v1(4043,5199) 4053,5209 4053,5232.79 C70.2@4063.65,5243.44
  Top Layer w16: C284.2@4034.53,5031.46 4050.46,5031.46 4064,5045 v1(4064,5106)
  Top Layer w20: C283.2@4034.53,4980.46 C284.2@4034.53,5031.46
  Bottom Layer w4: 3772.5,5429 v1(3782,5429)
  Bottom Layer w15: v1(3725,5410) 3729,5406 3749.5,5406 ; v1(3779,5508) 3784.99,5513.99 3784.99,5524 ; v1(3779,5586) 3784.99,5580.01 3784.99,5559
  Bottom Layer w20: 3580,5522 v1(3599,5522) ; v1(3599,5460.49) 3589.49,5470 3576.01,5470 ; v1(3599,5479) 3585.01,5479 3576.01,5470 ; 3604,5578.01 3604,5546 v1(3599,5541) 3577.29,5541 3576.01,5539.72 3576.01,5470 ; 3678,5646.47 3694,5630.47 v1(3694,5592) ; v1(3715,5592) 3715,5636.47 3725,5646.47 ; v1(3779,5508) 3779,5485.47 3783,5481.47
PWRON: C11.1 C97.2 R23.2 U4.6 | length 750.3
  Top Layer w4: C11.1@3681,5349.5 3673.36,5357.14 U4.6@3673.36,5385.61 3673.36,5393.36 v1(3689,5409)
  Top Layer w6: v2(4279,5371) 4279,5391 4289,5401 4306,5401 C97.2@4307,5402 4307.07,5401.93 R23.2@4307.07,5379.2
  内层4 w6: v1(3689,5409) 3705,5393 3775,5393 3781,5387 4263,5387 v2(4279,5371)
RF: C244.2 R72.1 U9.2 | length 145.5
  Top Layer w5: R72.1@3822.08,5986.22 C244.2@3844.57,5986.22 3965.43,5986.22 U9.2@3966.94,5987.73
RGMII0-CLKIN: U12.35 U14.C17 | length 1887.7
  Top Layer w3: U14.C17@6042.49,5355.41 6052.29,5345.61 6095.29,5345.65 6103.65,5354 6114,5354 6117,5357 6126,5357
  Top Layer w4: 6126,5357 6220,5357 v1(6263,5400)
  Top Layer w5: v1(5842,4350.9) U12.35@5871.6,4350.9
  内层2 w4: v1(5842,4350.9) 5848.9,4344 6171,4344 6195,4368 6195,4405 6439,4649 6439,5291 6334,5396 6267,5396 v1(6263,5400)
RGMII0-MDC: U12.13 U14.C16 | length 1713.8
  Top Layer w3: U14.C16@6042.49,5375.11 6052.31,5365.29 6066.18,5365.29 6069.95,5361.52 6090.74,5361.52 6099.09,5369.88 6099.86,5370.65 ; 6099.86,5370.73 6099.86,5371.05
  Top Layer w4: U12.13@6068.4,4303.6 6196.6,4303.6 v1(6199,4306) ; 6099.09,5369.88 6099.86,5370.73 6105.55,5377 6192,5377 v1(6216,5401)
  内层2 w4: v1(6199,4306) 6211,4318 6211,4400 6451,4640 6451,5297 6342,5406 6280,5406 6271,5415 6230,5415 v1(6216,5401)
RGMII0-MDIO: R83.2 U12.14 U14.B16 | length 1735.2
  Top Layer w3: U14.B16@6062.26,5375.16 6073.1,5386 6179,5386 6182,5389
  Top Layer w4: 6182,5389 v1(6194,5401)
  Top Layer w5: U12.14@6068.4,4319.4 6139.89,4319.4 R83.2@6140.49,4320 6140.49,4325.3 6152.19,4337 6193,4337 6211,4319 v1(6229,4319)
  内层2 w4: v1(6194,5401) 6219,5426 6280,5426 6289,5417 6350,5417 6463,5304 6463,4629 6226,4392 6226,4322 v1(6229,4319)
RGMII0-RXCK: R93.2 U12.27 U14.B14 | length 1679.7
  Top Layer w3: U14.B14@6062.19,5414.51 6068.52,5414.51 6078,5405.03 6085.87,5405.03 6097.7,5416.85 6115.15,5416.85 v1(6130,5402)
  Top Layer w5: U12.27@5946.4,4441.4 5946.4,4497.4 5954,4505 v1(5954,4513.49)
  内层2 w4: v1(5954,4513.49) 5963,4504.49 5963,4452 6001,4414 6124,4414 6390,4680 6390,5268 6307,5351 6181,5351 v1(6130,5402)
RGMII0-RXCTL: R95.2 U12.26 U14.D18 | length 1659.7
  Top Layer w5: U12.26@5962.1,4441.4 5962.1,4489.1 5976,4503 v1(5976,4513.49) ; U14.D18@6022.89,5335.78 v1(6022.89,5355.78)
  内层2 w4: v1(5976,4513.49) 5976,4456 6005,4427 6115,4427 6376,4688 6376,5266 6305,5337 6173,5337 6135,5375 6042.11,5375 v1(6022.89,5355.78)
RGMII0-RXD0: R89.1 U12.25 U14.E18 | length 1632.8
  Top Layer w5: U12.25@5977.9,4441.4 5977.9,4481.9 5999,4503 v1(5999,4513.49) ; U14.E18@6003.2,5335.78 v1(6003.2,5355.78)
  内层2 w4: v1(5999,4513.49) 5999,4508 5990,4499 5990,4459 6011,4438 6105,4438 6363,4696 6363,5260 6298,5325 6167,5325 6131,5361 6049,5361 6029,5341 6009.11,5341 6003.2,5346.9 v1(6003.2,5355.78)
RGMII0-RXD1: R86.2 U12.24 U14.F18 | length 1594
  Top Layer w5: U14.F18@5983.52,5335.78 v1(5983.52,5355.78) ; U12.24@5993.6,4441.4 5993.6,4475.6 6023.47,4505.47 v1(6023.47,4513.49)
  内层2 w4: v1(5983.52,5355.78) 5983.52,5350.48 6002.37,5331.63 6038.63,5331.63 6055,5348 6126,5348 6162,5312 6292,5312 6350,5254 6350,4705 6094,4449 6020,4449 6004,4465 6004,4494.02 v1(6023.47,4513.49)
RGMII0-RXD2: R82.2 U12.23 U14.D14 | length 1920.5
  Top Layer w5: U12.23@6009.4,4441.4 6009.4,4469.4 6047,4507 v1(6047,4513.49) ; U14.D14@6022.89,5414.53 v1(6022.89,5434.53)
  内层4 w4: v1(6022.89,5434.53) 6027.47,5434.53 6105,5357 6427,5357 6520,5264 6520,4594 6371,4445 6095,4445 6047,4493 v1(6047,4513.49)
RGMII0-RXD3: R91.1 U12.22 U14.E14 | length 1894.5
  Top Layer w5: U14.E14@6003.2,5414.53 v1(6003.2,5434.53) ; U12.22@6025.1,4441.4 6025.1,4463.1 6072,4510 v1(6072,4513.49)
  内层4 w4: v1(6003.2,5434.53) 6018.72,5419 6027,5419 6100,5346 6420,5346 6509,5257 6509,4598 6367,4456 6101,4456 6062,4495 6062,4503.49 v1(6072,4513.49)
RGMII0-TXCK: U12.20 U14.G12 | length 1984.7
  Top Layer w4: v1(5963,5435) 5963,5453.07 U14.G12@5963.82,5453.9 ; U12.20@6068.4,4413.9 6086.9,4413.9 6097,4424 6194,4424 6223,4395 6289,4395 6311,4417 6358,4417 v1(6373,4402)
  内层2 w3: v1(5963,5435) 5977,5449 6028,5449 6042,5435 6062,5435 6066,5439
  内层2 w4: 6066,5439 6084,5457 6179,5457 6199,5477 6307,5477 6317,5467 6379,5467 6515,5331 6515,4593 6373,4451 v1(6373,4402)
RGMII0-TXCTL: U12.19 U14.F14 | length 1914.8
  Top Layer w4: U12.19@6068.4,4398.1 6089.1,4398.1 6103,4412 6186,4412 6216,4382 6294,4382 6313,4401 v1(6348,4401)
  Top Layer w5: U14.F14@5983.52,5414.53 v1(5983.52,5434.53)
  内层2 w4: v1(5983.52,5434.53) 6000.05,5418 6065,5418 6092,5445 6184,5445 6203,5464 6299,5464 6309,5454 6372,5454 6502,5324 6502,4603 6358,4459 6358,4411 v1(6348,4401)
RGMII0-TXD0: U12.18 U14.E16 | length 1868.3
  Top Layer w4: U12.18@6068.4,4382.4 6094.4,4382.4 6110,4398 6182,4398 6212,4368 6302,4368 6319,4385 v1(6325,4385)
  Top Layer w5: U14.E16@6003.2,5375.16 v1(6003.2,5395.16)
  内层2 w4: v1(6003.2,5395.16) 6017.04,5409 6074,5409 6100,5435 6190,5435 6207,5452 6292,5452 6302,5442 6365,5442 6489,5318 6489,4611 6344,4466 6344,4420 6325,4401 v1(6325,4385)
RGMII0-TXD1: U12.17 U14.B17 | length 1572.5
  Top Layer w3: U14.B17@6062.19,5355.41 6065.19,5352.41 6092.44,5352.41 6107.03,5367 6121,5367
  Top Layer w4: U12.17@6068.4,4366.6 6106.6,4366.6 v1(6110,4370) ; 6121,5367 6206,5367 v1(6240,5401)
  内层2 w4: v1(6110,4370) 6120,4360 6169,4360 6181,4372 6181,4410 6428,4657 6428,5283 6326,5385 6256,5385 v1(6240,5401)
RGMII0-TXD2: U12.16 U14.A14 | length 1475.2
  Top Layer w3: U14.A14@6081.94,5414.53 6092.38,5425 6118.22,5425 6128.22,5415 6138,5415 v1(6151,5402)
  Top Layer w4: U12.16@6068.4,4350.9 6113.9,4350.9 v1(6142,4379)
  内层2 w4: v1(6142,4379) 6151,4388 6151,4420 6403,4672 6403,5272 6312,5363 6190,5363 v1(6151,5402)
RGMII0-TXD3: U12.15 U14.B13 | length 1536.8
  Top Layer w4: U14.B13@6062.26,5434.21 6063.47,5433 6124,5433 6134,5423 6151,5423 v1(6172,5402) ; U12.15@6068.4,4335.1 6124.1,4335.1 6165,4376 v1(6165,4379)
  内层2 w4: v1(6165,4379) 6165,4414 6416,4665 6416,5276 6318,5374 6200,5374 v1(6172,5402)
RGMII1-CLKIN: U13.35 U14.E2 | length 2323.8
  Top Layer w3: U14.E2@6003.09,5650.71 6013.4,5661.02 6013.4,5731.89 6036.9,5755.4 6036.9,5756.02
  Top Layer w4: 6037.03,5756 6096.03,5815 6562,5815 6658,5719 6658,5638 6666,5630 6666,5600 6654,5588 6635,5588 v1(6622,5575)
  Top Layer w6: v1(6558,4345.41) U13.35@6586.51,4345.41
  内层2 w4: v1(6558,4345.41) 6665,4452.41 6665,4486 6650,4501 6650,4531 6677,4558 6677,5331 6645,5363 6645,5489 6622,5512 v1(6622,5575)
RGMII1-MDC: U13.13 U14.H2 | length 2804.7
  Top Layer w3: U14.H2@5944.09,5650.71 5946.67,5653.29 5946.67,5680.46 5956.87,5690.67 5956.87,5743.75 5953.51,5747.11 5953.51,5762.87 5956.06,5765.42
  Top Layer w4: 5956.37,5765.09 5956.37,5802.52 6049.85,5896 6639,5896 6800,5735 6800,5524 6830,5494 6833,5494 v1(6850,5477) ; U13.13@6783.31,4298.11 6882.11,4298.11 6896,4312 6896,4350 v1(6909,4363)
  内层2 w4: v1(6850,5477) 6860,5487 6862,5487 6868,5493 6878,5493 6888,5483 6888,5470 6876,5458 6876,4606 6906,4576 6906,4521 6966,4461 6966,4410 6919,4363 v1(6909,4363)
RGMII1-MDIO: R101.2 U13.14 U14.H3 | length 2678.9
  Top Layer w3: U14.H3@5944.09,5631.01 5953.99,5640.91 5953.99,5677.14 5963.45,5686.6 5963.45,5756.58 5966.62,5759.75 5966.62,5781.91 5967.93,5783.23 ; 5968.16,5783.23 5968.16,5788.65
  Top Layer w4: 5968.16,5788.65 5968.16,5793.26 6058.9,5884 6629,5884 6786,5727 6786,5518 v1(6827,5477) ; R101.2@6853.49,4314 6853.49,4333.49 v1(6865,4345)
  Top Layer w6: U13.14@6783.31,4313.91 6853.4,4313.91 R101.2@6853.49,4314
  内层2 w4: v1(6827,5477) 6848,5456 6848,4598 6878,4568 6878,4506 6935,4449 6935,4424 6906,4395 6893,4395 6880,4382 6880,4360 v1(6865,4345)
RGMII1-RXCK: R111.2 U13.27 U14.J5 | length 2370.5
  Top Layer w4: U14.J5@5924.46,5591.69 v1(5944.46,5591.69)
  Top Layer w6: U13.27@6661.31,4435.91 6661.31,4502.8 v1(6666,4507.49)
  内层2 w4: v1(5944.46,5591.69) 5951.31,5591.69 5974,5569 5996,5569 6008,5581 6008,5776 6046,5814 6583,5814 6668,5729 6668,5662 6645,5639 6630,5639 6615,5624 6615,5604 6638,5581 6638,5518 6659,5497 6659,5369 6689.87,5338.13 6689.87,4547.87 6666,4524 v1(6666,4507.49)
RGMII1-RXCTL: R113.2 U13.26 U14.E1 | length 2146.8
  Top Layer w3: 6003.07,5686.02 6003.07,5733.29 6015.23,5745.46
  Top Layer w4: U14.E1@6003.07,5670.43 6003.07,5686.02 ; 6015.76,5745.46 6015.76,5749.53 6092.23,5826 6573,5826 6673,5726 6673,5646 6680,5639 6680,5596 6656,5572 v1(6656,5526)
  Top Layer w6: U13.26@6677.01,4435.91 6677.01,4487.01 6687,4497 v1(6687,4507.49)
  内层2 w4: v1(6656,5526) 6674,5508 6674,5375 6702,5347 6702,4541 6687,4526 v1(6687,4507.49)
RGMII1-RXD0: R107.1 U13.25 U14.D2 | length 2265.3
  Top Layer w3: U14.D2@6022.79,5650.71 6032.69,5660.61 6032.69,5720.69 6041,5729
  Top Layer w4: 6041,5729 6041,5731.91 6100.09,5791 6365.15,5791 6369.15,5787 6369.15,5777 6373.15,5773 6380.15,5773 6384.15,5777 6384.15,5787 6388.15,5791 6395.15,5791 6399.15,5787 6399.15,5777 6403.15,5773 6410.15,5773 6414.15,5777 6414.15,5787 6418.15,5791 6425.15,5791 6429.15,5787 6429.15,5777 6433.15,5773 6440.15,5773 6444.15,5777 6444.15,5787 6448.15,5791 6455.15,5791 6459.15,5787 6459.15,5777 6463.15,5773 6470.15,5773 6474.15,5777 6474.15,5787 6478.15,5791 6485.15,5791 6489.15,5787 6489.15,5777 6493.15,5773 6500.15,5773 6504.15,5777 6504.15,5787 6508.15,5791 6515.15,5791 6519.15,5787 6519.15,5777 6523.15,5773 6530.15,5773 6534.15,5777 6534.15,5787 6538.15,5791 6546,5791 6631,5706 6631,5681.85 6627,5677.85 6617,5677.85 6613,5673.85 6613,5666.85 6617,5662.85 6627,5662.85 6631,5658.85 6631,5651.85 6627,5647.85 6617,5647.85 6613,5643.85 6613,5636.85 6617,5632.85 6627,5632.85 6631,5628.85 v1(6631,5611)
  Top Layer w6: U13.25@6692.81,4435.91 6692.81,4479.81 6709,4496 v1(6709,4507.49)
  内层2 w4: v1(6631,5611) 6632,5611 6652,5591 6652,5554 6687,5519 6687,5384 6714,5357 6714,4534 6709,4529 v1(6709,4507.49)
RGMII1-RXD1: R104.2 U13.24 U14.D1 | length 2068.8
  Top Layer w3: U14.D1@6022.79,5670.41 6025.69,5673.31 6025.69,5726.99
  Top Layer w4: 6025.69,5726.99 6025.69,5729.27 ; 6025.75,5729.27 6099.48,5803 6553,5803 6644,5712 6644,5621 v1(6652,5613)
  Top Layer w6: U13.24@6708.51,4435.91 6708.51,4475.51 6732,4499 v1(6732,4507.49)
  内层2 w4: v1(6652,5613) 6665,5600 6665,5562 6700,5527 6700,5393 6727,5366 6727,4535 6732,4530 v1(6732,4507.49)
RGMII1-RXD2: R100.2 U13.23 U14.J4 | length 2376.3
  Top Layer w4: U14.J4@5924.46,5611.38 v1(5944.46,5611.38)
  Top Layer w6: U13.23@6724.31,4435.91 6724.31,4475.31 6754,4505 v1(6754,4507.49)
  内层2 w4: v1(5944.46,5611.38) 5977.84,5578 5990,5578 5998,5586 5998,5653 5994,5657 5994,5784 6038,5828 6589,5828 6681,5736 6681,5566 6713,5534 6713,5399 6739,5373 6739,4542 6754,4527 v1(6754,4507.49)
RGMII1-RXD3: R109.1 U13.22 U14.G5 | length 2351.8
  Top Layer w4: U14.G5@5963.83,5591.69 v1(5983.83,5611.69)
  Top Layer w6: U13.22@6740.01,4435.91 6740.01,4469.01 6776,4505 v1(6776,4507.49)
  内层2 w4: v1(5983.83,5611.69) 5969,5626.52 5969,5638 5982,5651 5982,5793 6032,5843 6595,5843 6696,5742 6696,5573 6728,5541 6728,5407 6752,5383 6752,4549 6776,4525 v1(6776,4507.49)
RGMII1-TXCK: U13.20 U14.G1 | length 2376.4
  Top Layer w3: U14.G1@5963.82,5670.43 5963.79,5674.65 5969.95,5680.81 5969.95,5749.27 5976.58,5755.91 5976.58,5761.72
  Top Layer w4: 5976.66,5761.66 5976.66,5782.83 6065.83,5872 6617,5872 6771,5718 6771,5584 v1(6741,5554) ; U13.20@6783.31,4408.41 6796.41,4408.41 6803,4415 v1(6803,4448)
  内层2 w4: v1(6741,5554) 6743,5552 6743,5412 6766,5389 6766,4559 6793,4532 6793,4458 v1(6803,4448)
RGMII1-TXCTL: U13.19 U14.G2 | length 2378.6
  Top Layer w3: U14.G2@5963.79,5650.71 5973.59,5660.51 5973.62,5673.96 5976.95,5677.28 5976.95,5744.9 5986.78,5754.74 5986.78,5763.78
  Top Layer w4: 5986.78,5763.78 5986.78,5774.1 6072.68,5860 6606,5860 6757,5709 6757,5596.66 6752.34,5592 v1(6754,5592) ; U13.19@6783.31,4392.61 6801.61,4392.61 6825,4416 v1(6825,4448)
  内层2 w4: v1(6754,5592) 6754,5567 6758,5563 6758,5420 6779,5399 6779,4565 6806,4538 6806,4467 v1(6825,4448)
RGMII1-TXD0: U13.18 U14.F2 | length 2357.3
  Top Layer w3: U14.F2@5983.39,5650.71 5993.2,5660.52 5993.2,5685.16 5995.16,5687.12 5995.16,5734.97 6006.75,5746.56 6006.75,5757.45
  Top Layer w4: 6006.23,5757 6087.23,5838 6583,5838 6687,5734 6687,5660 6710,5637 v1(6711,5637) ; U13.18@6783.31,4376.91 6806.91,4376.91 6847,4417 v1(6847,4448)
  内层2 w4: v1(6711,5637) 6723,5625 6756,5625 6772,5609 6772,5427 6793,5406 6793,4571 6819,4545 6819,4476 v1(6847,4448)
RGMII1-TXD1: U13.17 U14.F1 | length 2405.4
  Top Layer w3: U14.F1@5983.39,5670.41 5986.2,5673.22 5986.2,5741.02 5996.79,5751.61 5996.79,5765.46 5997.45,5766.09
  Top Layer w4: 5997.45,5766.09 6080.36,5849 6594,5849 6702,5741 6702,5668 6716,5654 6731,5654 v1(6739,5646) ; U13.17@6783.31,4361.11 6812.89,4361.11 6870,4418.23 v1(6870,4448)
  内层2 w4: v1(6739,5646) 6749,5636 6764,5636 6786,5614 6786,5436 6807,5415 6807,4577 6833,4551 6833,4485 v1(6870,4448)
RGMII1-TXD2: U13.16 U14.L5 | length 2613.8
  Top Layer w4: U14.L5@5885.09,5591.69 v1(5905.09,5591.69) ; U13.16@6783.31,4345.41 6817.41,4345.41 6892,4420 v1(6892,4448)
  内层2 w4: v1(5905.09,5591.69) 5920,5606.6 5920,5698 5939,5717 5939,5772 6028,5861 6600,5861 6755,5706 6755,5666 6800,5621 6800,5444 6820,5424 6820,4585 6848,4557 6848,4492 v1(6892,4448)
RGMII1-TXD3: U13.15 U14.L4 | length 2680.1
  Top Layer w4: U14.L4@5885.09,5611.38 v1(5905.09,5611.38) ; U13.15@6783.31,4329.61 6805.39,4329.61 6807,4328 6821,4328 v1(6864,4371)
  内层2 w4: v1(5905.09,5611.38) 5905.09,5701.09 5925,5721 5925,5777 6022,5874 6608,5874 6769,5713 6769,5674 6813,5630 6813,5456 6834,5435 6834,4592 6864,4562 6864,4500 6921,4443 6921,4431 6900,4410 6887,4410 6864,4387 v1(6864,4371)
SAA0: U14.AJ33 UD1.H2 | length 651.1
  Top Layer w3: v3(5508.11,5078.97) 5508.11,5076.78 5520.61,5064.28 5520.61,5050.2 U14.AJ33@5530.43,5040.38
  Top Layer w4.5: UD1.H2@4978.13,5225.67 4990.22,5237.77 5015.08,5237.77 5019.88,5232.97 5053.76,5232.97 5090.76,5195.97 5096.92,5195.97 v3(5110.92,5181.97)
  Inner5 w4.5: v3(5110.92,5181.97) 5130.86,5181.97 5166.86,5145.97 5177.92,5145.97 5208.92,5114.97 5372.92,5114.97 5411.92,5075.97 5505.11,5075.97 v3(5508.11,5078.97)
SAA1: U14.AJ32 UD1.J2 | length 680
  Top Layer w3: v3(5511.92,5099.97) 5521,5090.89 5521,5073.89 5530.43,5064.46 U14.AJ32@5530.43,5060.06
  Top Layer w4.5: UD1.J2@4978.13,5251.26 4992.26,5251.26 5003.97,5262.97 5018.88,5262.97 5024.52,5257.33 5031.28,5257.33 5039.92,5265.97 5053.92,5265.97 5095.92,5223.97 v3(5095.92,5210.97)
  Inner5 w3: 5481,5086.98 5494,5087 5498,5088 v3(5511.92,5099.97)
  Inner5 w4.5: v3(5095.92,5210.97) 5096.37,5210.97 5102.33,5205.01 5128.42,5204.92 5172.87,5160.47 5183.93,5160.47 5213.43,5130.97 5372.42,5130.97 5382.39,5121 5407.16,5121 5441.17,5086.98 5481,5086.98 ; v3@5510.37,5099.97 v3(5511.92,5099.97)
SAA2: U14.AG30 UD1.H9 | length 930.7
  Top Layer w4: UD1.H9@4757.66,5225.67 4758.62,5225.67 4771.66,5238.71 v3(4771.92,5238.71)
  Top Layer w4.5: v3(5551.92,5118.97) 5569.8,5101.09 U14.AG30@5569.8,5099.43
  Inner5 w3: 5475.79,5110.84 5478.94,5114 5516.89,5114 5524.92,5105.97 5536.92,5105.97 5549.92,5118.97 v3(5551.92,5118.97)
  Inner5 w4.5: v3(4771.92,5238.71) 4774.66,5235.97 4828.92,5235.97 4848.92,5255.97 4868.92,5255.97 4883.92,5240.97 4883.92,5232.47 4888.42,5227.97 4942.92,5227.97 4949.42,5221.47 5062.93,5221.47 5083.43,5241.97 5106.39,5241.97 5114.85,5233.51 5140.9,5233.46 5184.89,5189.47 5195.95,5189.47 5224.45,5160.97 5379.92,5160.97 5395.11,5145.78 5405.73,5145.78 5408.92,5148.97 5430.92,5148.97 5469.05,5110.84 5475.79,5110.84
SAA3: U14.AG29 UD1.H10 | length 1041.4
  Top Layer w4.5: UD1.H10@4726.16,5225.67 v3(4738.91,5238.44) ; v3(5551.92,5139.97) 5551.92,5138.97 5569.8,5121.09 U14.AG29@5569.8,5119.12
  内层2 w3: 5468.92,5145.97 5476.79,5153.85 5541.04,5153.85 5551.92,5142.97 v3(5551.92,5139.97)
  内层2 w4.5: v3(4738.91,5238.44) 4754.38,5222.97 4780.92,5222.97 4793.92,5235.97 4793.92,5280.97 4798.92,5285.97 4838.92,5285.97 4842.92,5281.97 4842.92,5236.97 4859.92,5219.97 4868.92,5219.97 4889.92,5198.97 4944.92,5198.97 4952.92,5206.97 4980.92,5206.97 5016.92,5170.97 5028.92,5170.97 5063.92,5135.97 5078.92,5135.97 5087.42,5127.47 5407.42,5127.47 5414.89,5120 5442.94,5120 5468.92,5145.97
SAA4: U14.AJ30 UD1.H11 | length 980.8
  Top Layer w4: UD1.H11@4694.68,5225.67 4709.92,5240.91 v3(4709.92,5241.97)
  Top Layer w4.5: U14.AJ30@5530.43,5099.43 v3(5530.43,5119.46)
  Inner5 w3: 5473.43,5120.97 5528.92,5120.97 v3(5530.43,5119.46)
  Inner5 w4.5: v3(4709.92,5241.97) 4709.92,5259.97 4729.92,5279.97 4760.92,5279.97 4766.92,5285.97 4873.92,5285.97 4878.92,5280.97 4878.92,5275.97 4890.92,5263.97 4905.92,5263.97 4927.92,5241.97 4988.92,5241.97 4994.92,5235.97 5056.92,5235.97 5077.42,5256.47 5112.4,5256.47 5120.88,5247.99 5146.91,5247.96 5190.9,5203.97 5201.97,5203.97 5229.96,5175.97 5404.92,5175.97 5418.92,5161.97 5432.43,5161.97 5473.43,5120.97
SAA5: U14.AJ31 UD1.J11 | length 1167.4
  Top Layer w4.5: UD1.J11@4694.67,5251.26 4694.67,5251.72 4708.91,5265.96 4708.91,5284.96 v3(4714.92,5290.97) ; U14.AJ31@5530.43,5079.75 5549.65,5098.97 v3(5549.92,5098.97)
  Inner5 w4.5: v3(4714.92,5290.97) 4734.92,5310.97 4734.92,5319.97 4810.92,5395.97 4878.92,5395.97 4889.92,5406.97 4909.92,5406.97 4917.92,5398.97 4938.92,5398.97 4945.92,5405.97 4966.03,5405.97 4975.92,5396.08 4975.92,5389.08 4989.03,5375.97 5027.92,5375.97 5059.42,5344.47 5135.08,5344.47 5197.07,5282.48 5222.07,5282.48 5238.58,5265.97 5398.92,5265.97 5413.92,5250.97 5422.92,5250.97 5475.92,5197.97 5475.92,5174.97 5485.92,5164.97 5548.03,5164.97 5565.92,5147.08 5565.92,5111.97 5552.92,5098.97 v3(5549.92,5098.97)
SAB0: U14.AJ25 UD1.R2 | length 912.6
  Top Layer w4.5: UD1.R2@4978.13,5404.81 4982.08,5404.81 v3(4993.92,5392.97) ; U14.AJ25@5530.42,5197.86 U14.AJ25@5531.97,5196.32 ; U14.AJ25@5530.43,5197.86 U14.AJ25@5531.97,5196.32 ; v3(5531.97,5179.6) U14.AJ25@5531.97,5196.32
  内层2 w3: 5473.92,5160.97 5517.92,5160.97 5531.97,5175.02 v3(5531.97,5179.6)
  内层2 w4.5: v3(4993.92,5392.97) 5008.92,5377.97 5008.92,5324.95 5116.9,5216.97 5128.41,5216.97 5168.92,5176.46 5168.92,5152.47 5181.42,5139.97 5187.28,5139.97 5191.78,5144.47 5191.78,5163.47 5196.28,5167.97 5202.28,5167.97 5206.78,5163.47 5206.78,5144.47 5211.28,5139.97 5217.28,5139.97 5221.78,5144.47 5221.78,5163.47 5226.28,5167.97 5232.28,5167.97 5236.78,5163.47 5236.78,5144.47 5241.28,5139.97 5268.19,5139.97 5272.69,5144.47 5272.69,5149.85 5277.19,5154.35 5283.19,5154.35 5287.69,5149.85 5287.69,5144.47 5292.19,5139.97 5298.19,5139.97 5302.69,5144.47 5302.69,5149.85 5307.19,5154.35 5313.19,5154.35 5317.69,5149.85 5317.69,5144.47 5322.19,5139.97 5328.19,5139.97 5332.69,5144.47 5332.69,5149.85 5337.19,5154.35 5343.19,5154.35 5347.69,5149.85 5347.69,5144.47 5352.19,5139.97 5358.19,5139.97 5362.69,5144.47 5362.69,5149.85 5367.19,5154.35 5373.19,5154.35 5377.69,5149.85 5377.69,5144.47 5382.19,5139.97 5411.92,5139.97 5427.92,5155.97 5452.92,5155.97 5457.92,5160.97 5473.92,5160.97
SAB1: U14.AH25 UD1.P2 | length 888.2
  Top Layer w4.5: UD1.P2@4978.13,5379.22 4982.38,5374.97 4995.92,5374.97 5003.92,5366.97 5013.92,5366.97 5021.17,5374.22 5041.67,5374.22 5054.92,5360.97 5068.67,5360.97 v3(5068.92,5361.22) ; U14.AH25@5550.11,5197.86 5552.97,5195.01 v3(5552.97,5179.6)
  内层2 w4.5: v3(5068.92,5361.22) 5068.92,5326.48 5074.03,5321.37 5080.39,5321.37 5084.92,5325.9 5084.92,5340.67 5091.23,5346.97 5105.92,5346.97 5114.92,5337.97 5114.92,5330.97 5093.12,5309.17 5093.12,5302.28 5134.93,5260.47 5150.42,5260.47 5196.92,5213.97 5277.35,5213.97 5281.85,5209.47 5281.85,5196.02 5286.35,5191.52 5292.35,5191.52 5296.85,5196.02 5296.85,5209.47 5301.35,5213.97 5307.35,5213.97 5311.85,5209.47 5311.85,5196.02 5316.35,5191.52 5322.35,5191.52 5326.85,5196.02 5326.85,5209.47 5331.35,5213.97 5337.35,5213.97 5341.85,5209.47 5341.85,5196.02 5346.35,5191.52 5352.35,5191.52 5356.85,5196.02 5356.85,5209.47 5361.35,5213.97 5397.92,5213.97 5415.89,5196 5536.57,5196 v3(5552.97,5179.6)
SAB2: U14.AL25 UD1.R9 | length 914
  Top Layer w4: UD1.R9@4757.67,5404.81 v3(4772.8,5419.95)
  Top Layer w4.5: v3(5491,5181) U14.AL25@5491,5197.81
  内层2 w4.5: v3(4772.8,5419.95) 4786.78,5405.97 4871.92,5405.97 4892.92,5426.97 4936.92,5426.97 4940.92,5422.97 5007.41,5422.97 5053.92,5376.46 5053.92,5320.97 5128.92,5245.97 5144.41,5245.97 5194.41,5195.97 5263.92,5195.97 5278.92,5180.97 5363.92,5180.97 5374.42,5191.47 5405.42,5191.47 5412.92,5183.97 5488.03,5183.97 v3(5491,5181)
SAB3: U14.AK25 UD1.R10 | length 996.8
  Top Layer w4.5: UD1.R10@4726.16,5404.81 4739,5391.97 4810.92,5391.97 v3(4835.92,5366.97) ; U14.AK25@5510.74,5197.86 5511.96,5196.64 v3(5511.96,5179.6)
  内层2 w3: 5451.92,5173.97 5471.92,5173.97 5477.89,5168 5500.35,5168 v3(5511.96,5179.6)
  内层2 w4.5: v3(4835.92,5366.97) 4859.92,5390.97 4874.92,5390.97 4891.92,5407.97 4908.92,5407.97 4922.92,5393.97 4935.92,5393.97 4949.92,5407.97 4999.9,5407.97 5038.92,5368.95 5038.92,5315.46 5122.91,5231.47 5134.42,5231.47 5184.92,5180.97 5258.92,5180.97 5273.92,5165.97 5373.92,5165.97 5384.92,5176.97 5404.92,5176.97 5411.92,5169.97 5447.92,5169.97 5451.92,5173.97
SAB4: U14.AJ27 UD1.R11 | length 1023
  Top Layer w4: UD1.R11@4694.67,5404.81 4694.67,5397.21 4706.92,5384.96 4706.92,5375.97 4715.92,5366.97 4731.03,5366.97 4742.92,5355.08 4742.92,5324.97 4750.92,5316.97 v3(4750.92,5315.97)
  Top Layer w4.5: U14.AJ27@5530.43,5158.49 5530.43,5142.46 v3(5531.92,5140.97)
  Inner5 w3: 5476.92,5130.97 5479.92,5127.97 5518.92,5127.97 v3(5531.92,5140.97)
  Inner5 w4.5: v3(4750.92,5315.97) 4765.92,5300.97 4917.92,5300.97 4945.92,5272.97 4945.92,5261.97 4952.17,5255.72 5030.67,5255.72 5045.92,5270.97 5118.41,5270.97 5126.91,5262.47 5152.92,5262.46 5196.91,5218.47 5207.98,5218.47 5235.48,5190.97 5406.92,5190.97 5423.92,5173.97 5434.92,5173.97 5476.92,5131.97 5476.92,5130.97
